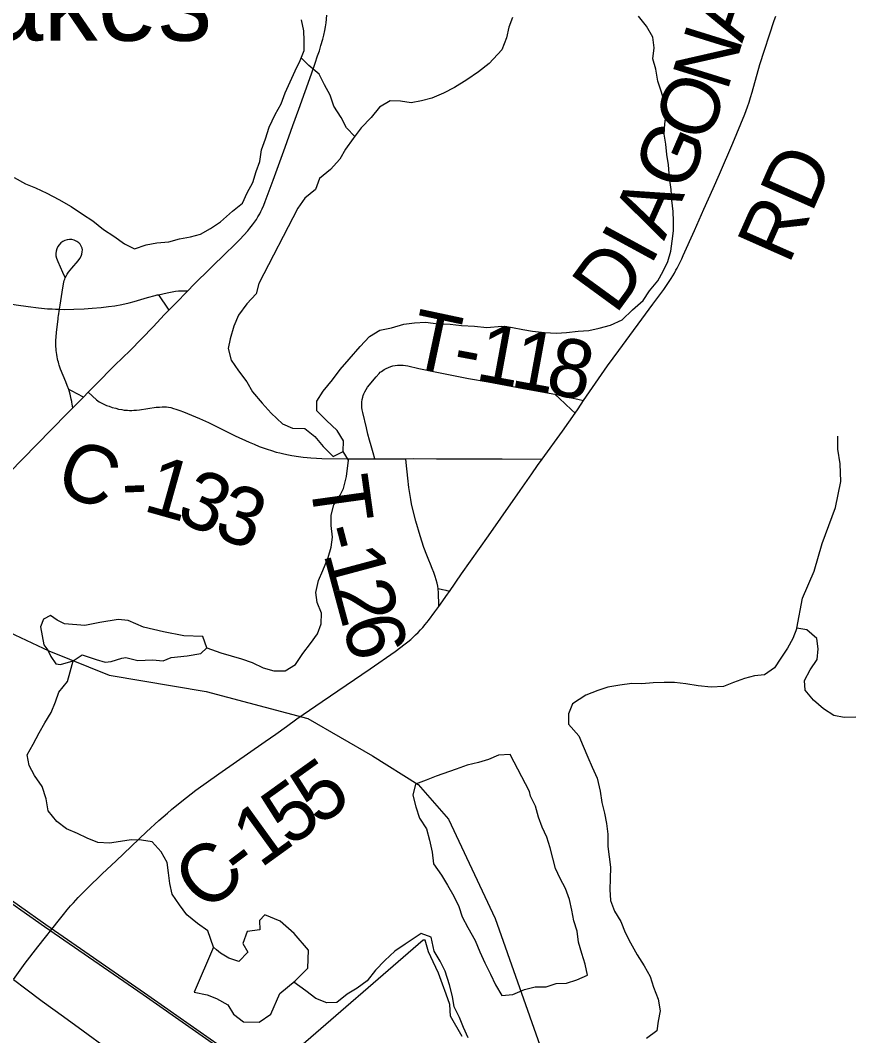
# Model space of a CAD drawing. Extents: x 0 to 34, y 0 to 22.
# Drawn here: x 2.781 to 3.589, y 16.134 to 17.124 of the extents above; entities that cross this region are included whole.
import ezdxf

# ---------------------------------------------------------------- set-up
doc = ezdxf.new("R2010")
doc.units = 0
for name, color, linetype in [('GM_X_County_Road', 7, 'Continuous'), ('GM_X_County_Road_Text', 7, 'Continuous'), ('GM_X_Major_Lake', 7, 'Continuous'), ('GM_X_Minor_Lake', 7, 'Continuous'), ('GM_X_Minor_River', 7, 'Continuous'), ('GM_X_Rail_Line', 7, 'Continuous'), ('GM_X_State_Route', 7, 'Continuous'), ('GM_X_Township_Road', 7, 'Continuous'), ('GM_X_Township_Road_Text', 7, 'Continuous'), ('GM_X_Unincorporated_Text', 7, 'Continuous')]:
    doc.layers.add(name, color=color, linetype=linetype)

msp = doc.modelspace()

# ---------------------------------------------------------------- linework, layer by layer
at = {"layer": 'GM_X_County_Road'}
msp.add_line((3.12652, 16.69641), (3.15662, 16.6965), dxfattribs=at)
for points in [[(3.32994, 16.75306), (3.35318, 16.78691), (3.36422, 16.80197), (3.39743, 16.847), (3.40806, 16.86151), (3.41533, 16.87225), (3.41688, 16.87477), (3.41855, 16.87747), (3.42001, 16.8801), (3.42121, 16.88228), (3.42238, 16.88469), (3.4241, 16.88801), (3.42568, 16.89137), (3.42712, 16.89448), (3.43823, 16.91876), (3.44732, 16.93979), (3.4564, 16.95975), (3.46238, 16.9738), (3.47535, 17.00394), (3.48719, 17.03226), (3.48849, 17.03589), (3.48979, 17.03943), (3.49148, 17.0441), (3.49284, 17.04866), (3.49432, 17.05359), (3.50171, 17.08056), (3.51573, 17.12375), (3.51724, 17.12795)], [(2.84702, 16.76137), (2.855, 16.75396), (2.85757, 16.75201), (2.85897, 16.75124), (2.86092, 16.75014), (2.86284, 16.7493), (2.86497, 16.74839), (2.86729, 16.7476), (2.87035, 16.74655), (2.87382, 16.74561), (2.87644, 16.74491), (2.87964, 16.74436), (2.88205, 16.74395), (2.88524, 16.74372), (2.88709, 16.74359), (2.88944, 16.74363), (2.89151, 16.74366), (2.89399, 16.74389), (2.89714, 16.74417), (2.91316, 16.74658), (2.91663, 16.74687), (2.91924, 16.74709), (2.92198, 16.74701), (2.92348, 16.74696), (2.92543, 16.74663), (2.92763, 16.74624), (2.93001, 16.74555), (2.93232, 16.74488), (2.93633, 16.74341), (2.93986, 16.74212), (2.95536, 16.73582), (2.96434, 16.73165), (2.99033, 16.71888), (3.00391, 16.71262), (3.00872, 16.71059), (3.01368, 16.70848), (3.01756, 16.7071), (3.02133, 16.70576), (3.02579, 16.7044), (3.0303, 16.70302), (3.03374, 16.70216), (3.03756, 16.70121), (3.04242, 16.70028), (3.04551, 16.69968), (3.05212, 16.69865), (3.05658, 16.69795), (3.06033, 16.69759), (3.06404, 16.69724), (3.06947, 16.69702), (3.07463, 16.69681), (3.10077, 16.69631), (3.12652, 16.69641)], [(3.32164, 16.74101), (3.32456, 16.74523), (3.32994, 16.75306)], [(3.28961, 16.69604), (3.30935, 16.72331), (3.32164, 16.74101)], [(3.15662, 16.6965), (3.16401, 16.69653), (3.18639, 16.69642), (3.25053, 16.69643), (3.28961, 16.69604)], [(3.19921, 16.56713), (3.21107, 16.58421), (3.23711, 16.62131), (3.24917, 16.63841), (3.26798, 16.66539), (3.27936, 16.6816), (3.28503, 16.68973), (3.28961, 16.69604)], [(3.18882, 16.55245), (3.19724, 16.5643), (3.19921, 16.56713)], [(2.92425, 16.35113), (2.92806, 16.35446), (2.93821, 16.36271), (2.95204, 16.37333), (2.97423, 16.38939), (3.01961, 16.42096), (3.02977, 16.42806), (3.04026, 16.43557), (3.05032, 16.44292), (3.07495, 16.4598), (3.12177, 16.49154), (3.14625, 16.50853), (3.15615, 16.51598), (3.15875, 16.51814), (3.16137, 16.52033), (3.16392, 16.5227), (3.16618, 16.52482), (3.16856, 16.52705), (3.17096, 16.52962), (3.17318, 16.532), (3.17559, 16.53491), (3.17869, 16.53866), (3.18501, 16.54708), (3.18882, 16.55245)], [(2.77406, 16.18893), (2.78566, 16.20475), (2.79783, 16.22068), (2.81902, 16.24747), (2.82296, 16.25233), (2.82646, 16.25665), (2.82988, 16.26055), (2.8326, 16.26365), (2.83725, 16.26866), (2.84147, 16.27294), (2.84641, 16.27795), (2.86065, 16.29181), (2.87423, 16.30455), (2.90395, 16.33284), (2.91585, 16.34381), (2.92425, 16.35113)], [(2.77406, 16.18893), (2.78606, 16.17986), (2.802, 16.16785), (2.82289, 16.15277), (2.842, 16.13891), (2.86512, 16.12206)]]:
    msp.add_lwpolyline(points, dxfattribs=at)
at = {"layer": 'GM_X_Major_Lake'}
msp.add_lwpolyline([(3.59527, 16.44469), (3.58392, 16.44422), (3.57406, 16.44604), (3.56379, 16.45278), (3.55426, 16.46105), (3.54586, 16.47084), (3.54541, 16.48032), (3.551, 16.4906), (3.55773, 16.50089), (3.55879, 16.51114), (3.5572, 16.52137), (3.54767, 16.52963), (3.53781, 16.53145), (3.53411, 16.52119), (3.52889, 16.51167), (3.52215, 16.50213), (3.51617, 16.49261), (3.50638, 16.48571), (3.49655, 16.48487), (3.48673, 16.48214), (3.47616, 16.47827), (3.46635, 16.4744), (3.45424, 16.47393), (3.44175, 16.47497), (3.42962, 16.47715), (3.41863, 16.4782), (3.40841, 16.4785), (3.39782, 16.47804), (3.38685, 16.4772), (3.37701, 16.4775), (3.36529, 16.47589), (3.35357, 16.47391), (3.34376, 16.47042), (3.33206, 16.46616), (3.31925, 16.45772), (3.31517, 16.44783), (3.31525, 16.43759), (3.32518, 16.42629), (3.32942, 16.41646), (3.33405, 16.4055), (3.33829, 16.39568), (3.34329, 16.3851), (3.34604, 16.3726), (3.34764, 16.36124), (3.35037, 16.35103), (3.35234, 16.3408), (3.35356, 16.33057), (3.35365, 16.31844), (3.35486, 16.30859), (3.35608, 16.29836), (3.35579, 16.28699), (3.35549, 16.27674), (3.35634, 16.26575), (3.3602, 16.25555), (3.36634, 16.24535), (3.37058, 16.23477), (3.37558, 16.22457), (3.38211, 16.21287), (3.38901, 16.2023), (3.39477, 16.19173), (3.39825, 16.18152), (3.40251, 16.1698), (3.40449, 16.15844), (3.40268, 16.14818), (3.40124, 16.13869), (3.39145, 16.13141)], dxfattribs=at)
at = {"layer": 'GM_X_Minor_Lake'}
for p, q in [((3.05129, 16.94062), (3.01326, 16.86714)), ((2.88365, 16.50288), (2.89541, 16.49994)), ((3.27716, 16.37207), (3.25833, 16.40833)), ((3.17346, 16.22718), (3.04452, 16.11546)), ((2.96914, 16.2203), (2.95018, 16.17654))]:
    msp.add_line(p, q, dxfattribs=at)
for points in [[(2.77476, 16.97071), (2.78579, 16.96435), (2.79566, 16.96063), (2.80668, 16.95541), (2.81846, 16.94906), (2.83025, 16.94232), (2.84128, 16.93482), (2.85155, 16.92846), (2.86183, 16.91981), (2.8721, 16.91345), (2.88238, 16.90594), (2.89226, 16.90109), (2.90358, 16.90497), (2.91379, 16.90695), (2.92551, 16.9078), (2.93609, 16.91091), (2.94667, 16.91289), (2.95649, 16.91524), (2.96629, 16.921), (2.97607, 16.92752), (2.98773, 16.93785), (2.99751, 16.94552), (3.00197, 16.95579), (3.00757, 16.96569), (3.01089, 16.97633), (3.01422, 16.98622), (3.01603, 16.99761), (3.01973, 17.00825), (3.02342, 17.01966), (3.02938, 17.03184), (3.03498, 17.0425), (3.03906, 17.05315), (3.04873, 17.07446), (3.05357, 17.08474), (3.05766, 17.09425), (3.05758, 17.10411), (3.05713, 17.11358), (3.05478, 17.12418)], [(3.26065, 17.12654), (3.25694, 17.11703), (3.25475, 17.10677), (3.2503, 17.09498), (3.23791, 17.08161), (3.22738, 17.07357), (3.21608, 17.0659), (3.20403, 17.05822), (3.19348, 17.05283), (3.18216, 17.04781), (3.17196, 17.04546), (3.16176, 17.04348), (3.15153, 17.04492), (3.14131, 17.04522), (3.13114, 17.03907), (3.12289, 17.02915), (3.11313, 17.01884), (3.10526, 17.00854), (3.09777, 16.99824), (3.09217, 16.98834), (3.08316, 16.97841), (3.07264, 16.9696), (3.06856, 16.95896), (3.05803, 16.95053), (3.05129, 16.94062)], [(3.09554, 16.70359), (3.09584, 16.71383), (3.0897, 16.72402), (3.0794, 16.7338), (3.06987, 16.74321), (3.06979, 16.75269), (3.07615, 16.76222), (3.08515, 16.77328), (3.09264, 16.78358), (3.10127, 16.7935), (3.11215, 16.80572), (3.12115, 16.81565), (3.13132, 16.8218), (3.14266, 16.82416), (3.15474, 16.82766), (3.16495, 16.82888), (3.17592, 16.82973), (3.18805, 16.82792), (3.19978, 16.82763), (3.21077, 16.8262), (3.22364, 16.82555), (3.23576, 16.8245), (3.25013, 16.82575), (3.26074, 16.82431), (3.2706, 16.8225), (3.28007, 16.82067), (3.29181, 16.81963), (3.30355, 16.81896), (3.31339, 16.81941), (3.32473, 16.82064), (3.33495, 16.82148), (3.34515, 16.82383), (3.3561, 16.82657), (3.36741, 16.83197), (3.37756, 16.84153), (3.38808, 16.85071), (3.39406, 16.86024), (3.40232, 16.86978), (3.40754, 16.8793), (3.41201, 16.88881), (3.41496, 16.8987), (3.41639, 16.90857), (3.41745, 16.91843), (3.41776, 16.92791), (3.4173, 16.93739), (3.41608, 16.94838), (3.41524, 16.95899), (3.41364, 16.97035), (3.41279, 16.98286), (3.41119, 16.99309), (3.40998, 17.00294), (3.40839, 17.01278), (3.40907, 17.02303), (3.4105, 17.0329), (3.4089, 17.0435), (3.4058, 17.05372), (3.40231, 17.06431), (3.40032, 17.07605), (3.39759, 17.08627), (3.39865, 17.09689), (3.39743, 17.1075), (3.39129, 17.11807), (3.38364, 17.12787)], [(3.01326, 16.86714), (3.01069, 16.85727), (3.00168, 16.84734), (2.99344, 16.83627), (2.98899, 16.82562), (2.98529, 16.81346), (2.98348, 16.80397), (2.98622, 16.79261), (2.99349, 16.78205), (3.00152, 16.7715), (3.00727, 16.76168), (3.01644, 16.75076), (3.02522, 16.74097), (3.03628, 16.73043), (3.04616, 16.72634), (3.05827, 16.72606), (3.06779, 16.71816), (3.0762, 16.70837), (3.08574, 16.69859), (3.09554, 16.70359)], [(2.89541, 16.49994), (2.90979, 16.50043), (2.92001, 16.49937), (2.92793, 16.50285), (2.94344, 16.50448), (2.95667, 16.50648), (2.96268, 16.51221), (2.95881, 16.52318), (2.94026, 16.5238), (2.92055, 16.52781), (2.90083, 16.53221), (2.88602, 16.53892), (2.87617, 16.53961), (2.8584, 16.53681), (2.84367, 16.53405), (2.82397, 16.53541), (2.81675, 16.53915), (2.81028, 16.54365), (2.8035, 16.54018), (2.80053, 16.53257), (2.8037, 16.51516), (2.80752, 16.50988), (2.8106, 16.50384), (2.81557, 16.49667), (2.82012, 16.49595), (2.83221, 16.49945), (2.84124, 16.50521), (2.8549, 16.50077), (2.86363, 16.49818), (2.8693, 16.49898), (2.87987, 16.5021), (2.88365, 16.50288)], [(3.25833, 16.40833), (3.24698, 16.40749), (3.23717, 16.40324), (3.22736, 16.40051), (3.2164, 16.39777), (3.20583, 16.39389), (3.18621, 16.38692), (3.1764, 16.38305), (3.16621, 16.37918), (3.16364, 16.36854), (3.16638, 16.35719), (3.16987, 16.34622), (3.17677, 16.33565), (3.17988, 16.32468), (3.18225, 16.31295), (3.18347, 16.30158), (3.1915, 16.29064), (3.19726, 16.28083), (3.2034, 16.27026), (3.2084, 16.26006), (3.21151, 16.24985), (3.21726, 16.23965), (3.22418, 16.22681), (3.2288, 16.21585), (3.23381, 16.20527), (3.23919, 16.19394), (3.2442, 16.18374), (3.25033, 16.17317), (3.26092, 16.17439), (3.27224, 16.17903), (3.28282, 16.18176), (3.29341, 16.18184), (3.30323, 16.18495), (3.31344, 16.18541), (3.32326, 16.18852), (3.33382, 16.19315), (3.33147, 16.20375), (3.32836, 16.21435), (3.32486, 16.22531), (3.32364, 16.23592), (3.32054, 16.24614), (3.31856, 16.25636), (3.31621, 16.26696), (3.31234, 16.27755), (3.30697, 16.28737), (3.30272, 16.29719), (3.3, 16.30703), (3.29727, 16.31725), (3.29416, 16.32746), (3.28954, 16.33728), (3.28606, 16.34712), (3.28295, 16.35771), (3.27833, 16.36753), (3.27716, 16.37207)], [(2.95018, 16.17654), (2.96306, 16.17399), (2.97218, 16.17026), (2.9832, 16.16428), (2.98857, 16.15522), (2.99847, 16.14772), (3.01361, 16.14745), (3.0249, 16.15512), (3.03383, 16.17529), (3.04887, 16.18754), (3.06127, 16.19977), (3.06188, 16.2176), (3.04775, 16.23379), (3.03403, 16.24582), (3.01922, 16.25177), (3.01397, 16.24642), (3.01442, 16.23733), (3.00194, 16.23571), (2.99787, 16.22393), (3.00248, 16.21562), (2.99384, 16.20645), (2.98398, 16.20979), (2.97599, 16.21466), (2.97218, 16.21766), (2.96914, 16.2203)], [(3.21166, 16.13344), (3.20015, 16.15306), (3.19969, 16.16444), (3.19582, 16.17465), (3.19234, 16.18448), (3.18847, 16.19506), (3.18346, 16.20602), (3.17885, 16.21585), (3.17535, 16.22719), (3.17346, 16.22718)]]:
    msp.add_lwpolyline(points, dxfattribs=at)
at = {"layer": 'GM_X_Minor_River'}
for points in [[(3.10678, 17.01052), (3.09874, 17.0191), (3.09375, 17.02892), (3.08647, 17.04024), (3.08298, 17.05084), (3.07722, 17.06103), (3.07222, 17.07123), (3.06193, 17.07987), (3.05459, 17.08711)], [(3.53781, 16.53145), (3.54326, 16.56069), (3.55479, 16.58695), (3.56253, 16.61393), (3.5755, 16.64892), (3.5806, 16.67436), (3.58008, 16.69142), (3.5777, 16.70581), (3.57798, 16.71833)], [(2.96268, 16.51221), (2.97634, 16.50739), (2.98621, 16.50443), (2.99645, 16.50148), (3.0067, 16.49777), (3.01771, 16.49254), (3.02796, 16.48959), (3.03893, 16.48967), (3.0491, 16.49582), (3.05621, 16.50649), (3.0637, 16.51641), (3.07044, 16.52594), (3.07415, 16.53545), (3.07444, 16.54607), (3.0702, 16.55627), (3.06899, 16.56612), (3.07154, 16.5779), (3.07563, 16.58741), (3.08083, 16.60034), (3.08378, 16.61022), (3.08522, 16.62009), (3.08399, 16.63146), (3.08391, 16.64132), (3.08648, 16.65157), (3.09266, 16.66097), (3.09593, 16.6675), (3.09873, 16.67916), (3.10061, 16.69502), (3.09554, 16.70359)], [(2.96914, 16.2203), (2.96371, 16.23618), (2.95344, 16.2433), (2.94315, 16.25195), (2.93588, 16.26175), (2.92899, 16.27193), (2.92664, 16.28253), (2.92542, 16.29276), (2.92383, 16.30299), (2.91807, 16.31318), (2.90929, 16.32297), (2.89905, 16.32479), (2.88883, 16.32509), (2.87863, 16.32349), (2.86766, 16.32189), (2.8563, 16.32256), (2.84605, 16.32666), (2.83656, 16.33113), (2.82592, 16.3356), (2.8164, 16.34273), (2.808, 16.35328), (2.80601, 16.36502), (2.80213, 16.37713), (2.79448, 16.38768), (2.78948, 16.3975), (2.78751, 16.40773), (2.79348, 16.41839), (2.79907, 16.42943), (2.80467, 16.43895), (2.81103, 16.44924), (2.81511, 16.45951), (2.81844, 16.46901), (2.82669, 16.47931), (2.82926, 16.48881), (2.83221, 16.49945)], [(3.21735, 16.13196), (3.21273, 16.14216), (3.20887, 16.15199), (3.20387, 16.1622), (3.20227, 16.17242), (3.19916, 16.18377), (3.19489, 16.19701), (3.19027, 16.20683), (3.18414, 16.21664), (3.18149, 16.23013), (3.17175, 16.23372), (3.15608, 16.22325), (3.14591, 16.21635), (3.13614, 16.20755), (3.12714, 16.198), (3.11889, 16.1877), (3.10911, 16.18042), (3.09931, 16.17466), (3.08953, 16.16662), (3.0797, 16.16616), (3.06907, 16.17025), (3.05917, 16.17776), (3.04748, 16.1864)]]:
    msp.add_lwpolyline(points, dxfattribs=at)
at = {"layer": 'GM_X_Rail_Line'}
for points in [[(2.1, 17.12013), (2.10054, 17.11949), (2.17525, 17.03417), (2.26176, 16.91867), (2.30634, 16.86879), (2.36664, 16.81235), (2.48988, 16.71389), (2.59739, 16.63905), (2.68785, 16.57341), (2.75866, 16.53271), (2.80848, 16.50907), (2.86749, 16.48543), (2.9619, 16.46964), (3.0612, 16.44331), (3.12429, 16.40702), (3.16858, 16.37879), (3.1981, 16.3452), (3.24371, 16.24847), (3.28931, 16.1195), (3.32016, 16.04561), (3.3376, 16.01873), (3.47588, 15.90277), (3.58094, 15.84467), (3.67315, 15.78836)], [(3.61533, 15.77286), (3.52149, 15.81821), (3.4176, 15.86849), (3.34519, 15.90428), (3.26563, 15.94335), (3.20713, 15.97485), (3.16233, 16.00062), (3.14085, 16.01371), (3.11508, 16.02946), (3.08931, 16.04583), (3.0484, 16.07303), (2.90194, 16.17571), (2.80581, 16.24219), (2.75385, 16.2786), (2.68676, 16.32544), (2.58357, 16.39765), (2.43456, 16.50196), (2.33535, 16.5711), (2.25895, 16.62459), (2.17591, 16.68237), (2.1, 16.73576)], [(3.61429, 15.77076), (3.52046, 15.81611), (3.41657, 15.86639), (3.34416, 15.90219), (3.26455, 15.94128), (3.20598, 15.97281), (3.16113, 15.99862), (3.13963, 16.01172), (3.11384, 16.02748), (3.08803, 16.04387), (3.04707, 16.07111), (2.9006, 16.1738), (2.80446, 16.24028), (2.75251, 16.27669), (2.68541, 16.32353), (2.58222, 16.39574), (2.43321, 16.50005), (2.33401, 16.56919), (2.25761, 16.62268), (2.17456, 16.68046), (2.1, 16.7329)]]:
    msp.add_lwpolyline(points, dxfattribs=at)
at = {"layer": 'GM_X_State_Route'}
msp.add_lwpolyline([(2.77029, 16.6831), (2.79668, 16.71015), (2.82636, 16.74042), (2.83199, 16.74614), (2.84226, 16.75655), (2.84702, 16.76137), (2.85404, 16.76849), (2.87303, 16.78767), (2.88777, 16.80205), (2.91018, 16.82512), (2.92149, 16.8369), (2.92574, 16.84124), (2.93204, 16.84765), (2.94417, 16.86025), (2.95011, 16.86641), (2.9822, 16.89791), (2.98768, 16.90294), (2.99468, 16.91), (2.99871, 16.91444), (3.0026, 16.91873), (3.00459, 16.92121), (3.00731, 16.92457), (3.00905, 16.92702), (3.01095, 16.92967), (3.01244, 16.93216), (3.01419, 16.93506), (3.01538, 16.93742), (3.01673, 16.94011), (3.01822, 16.94368), (3.01963, 16.94704), (3.02726, 16.9681), (3.03897, 17.00021), (3.04647, 17.0213), (3.05221, 17.03707), (3.06462, 17.0715), (3.0682, 17.08188), (3.07068, 17.08918), (3.07233, 17.0939), (3.07387, 17.09921), (3.07562, 17.10526), (3.07663, 17.10936), (3.07771, 17.11377), (3.07837, 17.11757), (3.07901, 17.12119), (3.07964, 17.12869)], dxfattribs=at)
at = {"layer": 'GM_X_Township_Road'}
for points in [[(2.81892, 16.84212), (2.81951, 16.84601), (2.82219, 16.86303), (2.82316, 16.8685), (2.82362, 16.87009), (2.82407, 16.87152), (2.82459, 16.87275), (2.82541, 16.87439), (2.82641, 16.8762), (2.82777, 16.87815), (2.83113, 16.88231), (2.83712, 16.88932), (2.83889, 16.89174), (2.84001, 16.89379), (2.8408, 16.89597), (2.84124, 16.89825), (2.8413, 16.89996), (2.84102, 16.9016), (2.8402, 16.90372), (2.839, 16.90568), (2.83786, 16.90692), (2.83597, 16.90816), (2.83328, 16.90943), (2.83107, 16.91007), (2.8288, 16.91023), (2.82652, 16.90993), (2.82431, 16.90925), (2.82224, 16.90818), (2.82038, 16.90678), (2.81878, 16.90509), (2.81743, 16.90317), (2.81639, 16.90107), (2.8157, 16.89886), (2.81539, 16.89656), (2.81549, 16.89425), (2.816, 16.89198), (2.81732, 16.88861), (2.82183, 16.87839), (2.82404, 16.87354)], [(2.74525, 16.85514), (2.75041, 16.85305), (2.75616, 16.85119), (2.76106, 16.84961), (2.76851, 16.8479), (2.77665, 16.84642), (2.78857, 16.84469), (2.79861, 16.84354), (2.80727, 16.84271), (2.81178, 16.84245), (2.81505, 16.84227), (2.81892, 16.84212)], [(2.81892, 16.84212), (2.8241, 16.84195), (2.83307, 16.8422), (2.84299, 16.84267), (2.851, 16.84329), (2.85975, 16.84395), (2.86677, 16.84474), (2.87287, 16.84555), (2.87961, 16.84679), (2.88685, 16.84843), (2.89176, 16.8498), (2.89839, 16.85173), (2.90487, 16.8536), (2.91222, 16.85566), (2.91407, 16.85606), (2.91553, 16.85629)], [(2.91553, 16.85629), (2.92387, 16.85811), (2.93223, 16.85967), (2.93495, 16.86002), (2.93645, 16.86006), (2.93859, 16.86025), (2.94417, 16.86025)], [(2.91553, 16.85629), (2.91814, 16.85243), (2.92243, 16.84611), (2.92574, 16.84124)], [(2.82802, 16.76407), (2.82654, 16.76779), (2.82504, 16.77154), (2.82009, 16.78364), (2.81938, 16.78572), (2.81871, 16.78769), (2.81828, 16.78899), (2.81791, 16.79043), (2.81749, 16.79211), (2.81704, 16.79388), (2.81674, 16.7957), (2.81637, 16.79796), (2.81603, 16.80008), (2.81587, 16.80187), (2.81571, 16.80368), (2.81553, 16.80571), (2.81553, 16.80725), (2.81553, 16.80907), (2.81553, 16.81137), (2.81613, 16.81947), (2.81758, 16.83292), (2.81773, 16.83433), (2.81793, 16.83566), (2.81892, 16.84212)], [(3.12652, 16.69641), (3.12486, 16.70234), (3.12297, 16.70906), (3.12132, 16.71446), (3.11974, 16.72049), (3.11821, 16.72659), (3.1146, 16.74151), (3.11409, 16.74417), (3.11382, 16.74627), (3.11378, 16.74773), (3.11378, 16.74976), (3.11391, 16.75166), (3.11421, 16.75413), (3.11469, 16.75644), (3.11518, 16.75813), (3.11575, 16.75979), (3.11677, 16.76182), (3.11785, 16.76384), (3.11938, 16.76626), (3.12758, 16.77635), (3.13052, 16.77957), (3.13176, 16.78073), (3.13285, 16.78161), (3.13417, 16.78257), (3.13539, 16.78333), (3.1376, 16.78453), (3.13971, 16.78544), (3.14195, 16.78627), (3.14407, 16.78688), (3.14616, 16.78722), (3.14839, 16.78751), (3.15047, 16.78771), (3.15226, 16.78776), (3.15421, 16.78761), (3.1562, 16.78738), (3.15851, 16.78699), (3.16938, 16.78436), (3.18686, 16.7807), (3.2179, 16.77472), (3.23701, 16.77131), (3.27122, 16.76488), (3.29631, 16.76043), (3.30183, 16.75927)], [(2.83199, 16.74614), (2.83141, 16.74973), (2.83113, 16.75144), (2.83093, 16.75236), (2.83046, 16.75452), (2.82977, 16.75766), (2.82939, 16.75942), (2.82873, 16.76165), (2.82802, 16.76407)], [(2.84226, 16.75655), (2.8361, 16.75972), (2.83126, 16.76233), (2.82802, 16.76407)], [(3.30183, 16.75927), (3.31212, 16.75713), (3.32424, 16.75436), (3.32994, 16.75306)], [(3.30183, 16.75927), (3.30663, 16.75502), (3.31211, 16.75013), (3.31828, 16.74422), (3.32164, 16.74101)], [(3.18831, 16.5697), (3.18794, 16.57229), (3.18715, 16.57513), (3.18631, 16.57837), (3.18526, 16.58158), (3.18391, 16.58558), (3.18247, 16.58952), (3.18055, 16.59384), (3.17892, 16.59759), (3.17699, 16.60252), (3.17406, 16.61002), (3.17049, 16.62128), (3.16636, 16.63561), (3.16318, 16.64821), (3.16231, 16.65255), (3.16144, 16.65688), (3.16057, 16.66255), (3.15968, 16.66843), (3.15875, 16.67739), (3.15705, 16.69265), (3.15662, 16.6965)], [(3.18882, 16.55245), (3.18867, 16.55617), (3.18855, 16.56304), (3.18843, 16.56563), (3.18831, 16.5697)], [(3.19921, 16.56713), (3.19593, 16.56793), (3.19226, 16.56883), (3.18831, 16.5697)]]:
    msp.add_lwpolyline(points, dxfattribs=at)

# ---------------------------------------------------------------- texts
at = {"layer": 'GM_X_County_Road_Text'}
for s, height, rotation, p in [('A', 0.05682, 71.10945, (3.48456, 17.10095)), ('N', 0.05682, 72.71998, (3.4698, 17.05347)), ('O', 0.05682, 68.3826, (3.44976, 17.00241)), ('G', 0.05682, 66.54232, (3.42903, 16.95457)), ('RD', 0.056818, 66.08675, (3.52992, 16.88466)), ('A', 0.05682, 65.96176, (3.40835, 16.90819)), ('I', 0.05682, 61.47334, (3.39515, 16.88352)), ('D', 0.05682, 53.85191, (3.36116, 16.83605)), ('C', 0.05682, 339.58374, (2.81258, 16.66481)), ('1', 0.05682, 344.31265, (2.89912, 16.64618)), ('3', 0.05682, 335.69775, (2.9307, 16.63749)), ('-', 0.05682, 2.32861, (2.88048, 16.64469)), ('3', 0.05682, 340.63686, (2.96756, 16.6211)), ('5', 0.05682, 35.61148, (3.07163, 16.33755)), ('5', 0.05682, 35.64475, (3.0432, 16.31716)), ('1', 0.05682, 35.84257, (3.01487, 16.2967)), ('C', 0.05682, 41.34086, (2.96237, 16.25267)), ('-', 0.05682, 37.19307, (2.99657, 16.28281))]:
    msp.add_text(s, height=height, rotation=rotation, dxfattribs=at).set_placement(p)
at = {"layer": 'GM_X_Township_Road_Text'}
for s, rotation, p in [('T', 347.99841, (3.15736, 16.78719)), ('1', 349.54591, (3.22322, 16.77379)), ('1', 349.60887, (3.25743, 16.76748)), ('8', 347.86659, (3.29114, 16.76131)), ('-', 349.4107, (3.20034, 16.77807)), ('T', 277.92133, (3.06287, 16.67612)), ('-', 284.56838, (3.07012, 16.62706)), ('1', 285.03251, (3.07606, 16.6042)), ('2', 285.1072, (3.08509, 16.57058)), ('6', 285.10987, (3.09414, 16.53706))]:
    msp.add_text(s, height=0.05682, rotation=rotation, dxfattribs=at).set_placement(p)
at = {"layer": 'GM_X_Unincorporated_Text'}
msp.add_text('Lakes', height=0.078977, rotation=0.00001, dxfattribs=at).set_placement((2.6859, 17.10394))

doc.saveas('drawing.dxf')
